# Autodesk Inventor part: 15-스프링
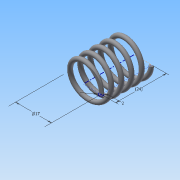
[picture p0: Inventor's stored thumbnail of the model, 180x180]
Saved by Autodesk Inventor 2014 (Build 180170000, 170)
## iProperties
Created: 2016-01
Part Number: 15-스프링
Material: 강철, 탄소
Document SubType Name: Modeling
Designer: Administrator
Density: 7.87 g/cm^3
Appearance: 반연마
Mass: 6.47306 g
Surface Area: 16.7315 cm^2
Volume: 0.822499 cm^3
Author: Administrator
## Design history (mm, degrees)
sketch "스케치1"
  geometry: L1 (0, 0)-(8.5, 0); L2 (8.5, 0)-(8.5, 20.5); L3 (8.5, 20.5)-(0, 20.5); L4 (0, 20.5)-(0, 0); C1 r 1 at (8.5, 0)
  constraints: 8 end point, 2 parallel, 1 centre point, 1 coincident, 1 horizontal, 1 perpendicular
  dimensions: "d0" = 17 diameter of L2 L4; "d1" = 20.5 distance of L1.end L2.end (derived); "d2" = 2 diameter of C1
feature "코일1" sketch "스케치1" pitch "d3" = 10; turns "d5" = 5; dims "d4" = 20.5 (= d1), "d6" = 0, angle "d7" = 90 deg, angle "d8" = 90 deg, "d9" = 0, "d10" = 0
node "작업 평면2"
sketch "스케치2"
  geometry: L1 (-7.5, 0)-(-9.5, 0) reference; 1 further point
  constraints: 1 horizontal alignment
extrude "돌출1" cut sketch "스케치2" distance "d13" = 10; taper "d14" = 0 deg
node "작업 평면3"
sketch "스케치3"
  geometry: L1 (-9.5, 0)-(-7.5, 0) reference; 1 further point
  constraints: 1 horizontal alignment
extrude "돌출2" cut sketch "스케치3" distance "d16" = 10; taper "d17" = 0 deg
node "솔리드1"
node "절단 모서리 투영1"
node "절단 모서리 투영2"
other parameters: "d12" = 0, "d15" = 20.5 (= d1)
